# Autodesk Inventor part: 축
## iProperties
Company: 한국ATC센터
Created: 2015-04
Part Number: 축
Document SubType Name: Modeling
Designer: KYOUNG IL JANG
Density: 7.85 g/cm^3
Material: 강
Author: KYOUNG IL JANG
